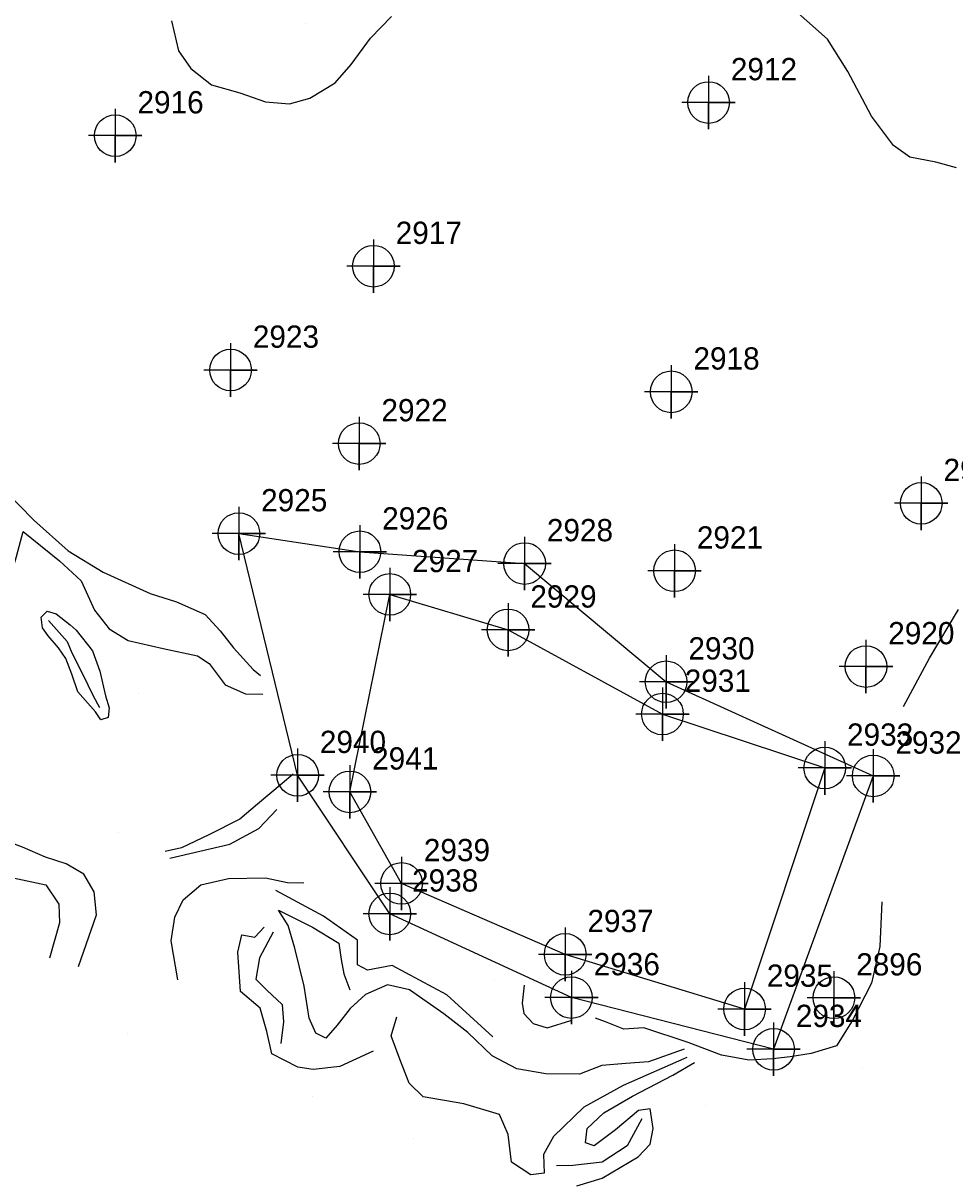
# Model space of a CAD drawing. Extents: x 2062781 to 2066835, y 358981 to 366501.
# Drawn here: x 2064945.6 to 2065050.3, y 363663.1 to 363793 of the extents above; entities that cross this region are included whole.
import ezdxf

# ---------------------------------------------------------------- set-up
doc = ezdxf.new("R2010")
doc.units = 0
for name, color, linetype in [('Exist DTM Breakline', 7, 'Continuous'), ('Exist DTM Breakline Cogo Number', 7, 'Continuous'), ('Exist DTM Breakline Cogo Point CELL', 7, 'Continuous'), ('Exist DTM Regular Point CELL', 7, 'Continuous'), ('Exist DTM Regular Point Cogo Number', 7, 'Continuous'), ('Exist DTM Ridgeline', 7, 'Continuous'), ('Exist DTM Ridgeline Cogo Number', 7, 'Continuous'), ('Exist DTM Ridgeline Cogo Point CELL', 7, 'Continuous'), ('PH Exist DTM Breakline', 7, 'Continuous'), ('PH Exist DTM Point', 7, 'Continuous')]:
    doc.layers.add(name, color=color, linetype=linetype)

msp = doc.modelspace()

# ---------------------------------------------------------------- linework, layer by layer
at = {"layer": 'Exist DTM Breakline'}
msp.add_lwpolyline([(2064986.8, 363728.86), (2065000.09, 363724.88), (2065017.43, 363715.42), (2065035.66, 363709.37), (2065026.65, 363682.3), (2065006.5, 363688.44), (2064988.12, 363696.4), (2064982.31, 363706.69), (2064986.8, 363728.86)], dxfattribs=at)
at = {"layer": 'Exist DTM Breakline Cogo Point CELL'}
for points in [[(2064986.8, 363731.86), (2064986.8, 363725.86), (2064986.8, 363728.86), (2064989.8, 363728.86), (2064983.8, 363728.86)], [(2064986.8, 363731.86), (2064986.8, 363725.86), (2064986.8, 363728.86), (2064989.8, 363728.86), (2064983.8, 363728.86)], [(2064986.8, 363731.86), (2064986.8, 363725.86), (2064986.8, 363728.86), (2064989.8, 363728.86), (2064983.8, 363728.86)], [(2065000.09, 363727.88), (2065000.09, 363721.88), (2065000.09, 363724.88), (2065003.09, 363724.88), (2064997.09, 363724.88)], [(2065000.09, 363727.88), (2065000.09, 363721.88), (2065000.09, 363724.88), (2065003.09, 363724.88), (2064997.09, 363724.88)], [(2065000.09, 363727.88), (2065000.09, 363721.88), (2065000.09, 363724.88), (2065003.09, 363724.88), (2064997.09, 363724.88)], [(2065017.43, 363718.42), (2065017.43, 363712.42), (2065017.43, 363715.42), (2065020.43, 363715.42), (2065014.43, 363715.42)], [(2065017.43, 363718.42), (2065017.43, 363712.42), (2065017.43, 363715.42), (2065020.43, 363715.42), (2065014.43, 363715.42)], [(2065017.43, 363718.42), (2065017.43, 363712.42), (2065017.43, 363715.42), (2065020.43, 363715.42), (2065014.43, 363715.42)], [(2065035.66, 363712.37), (2065035.66, 363706.37), (2065035.66, 363709.37), (2065038.66, 363709.37), (2065032.66, 363709.37)], [(2065035.66, 363712.37), (2065035.66, 363706.37), (2065035.66, 363709.37), (2065038.66, 363709.37), (2065032.66, 363709.37)], [(2065035.66, 363712.37), (2065035.66, 363706.37), (2065035.66, 363709.37), (2065038.66, 363709.37), (2065032.66, 363709.37)], [(2064982.31, 363709.69), (2064982.31, 363703.69), (2064982.31, 363706.69), (2064985.31, 363706.69), (2064979.31, 363706.69)], [(2064982.31, 363709.69), (2064982.31, 363703.69), (2064982.31, 363706.69), (2064985.31, 363706.69), (2064979.31, 363706.69)], [(2064982.31, 363709.69), (2064982.31, 363703.69), (2064982.31, 363706.69), (2064985.31, 363706.69), (2064979.31, 363706.69)], [(2064988.12, 363699.4), (2064988.12, 363693.4), (2064988.12, 363696.4), (2064991.12, 363696.4), (2064985.12, 363696.4)], [(2064988.12, 363699.4), (2064988.12, 363693.4), (2064988.12, 363696.4), (2064991.12, 363696.4), (2064985.12, 363696.4)], [(2064988.12, 363699.4), (2064988.12, 363693.4), (2064988.12, 363696.4), (2064991.12, 363696.4), (2064985.12, 363696.4)], [(2065006.5, 363691.44), (2065006.5, 363685.44), (2065006.5, 363688.44), (2065009.5, 363688.44), (2065003.5, 363688.44)], [(2065006.5, 363691.44), (2065006.5, 363685.44), (2065006.5, 363688.44), (2065009.5, 363688.44), (2065003.5, 363688.44)], [(2065006.5, 363691.44), (2065006.5, 363685.44), (2065006.5, 363688.44), (2065009.5, 363688.44), (2065003.5, 363688.44)], [(2065026.65, 363685.3), (2065026.65, 363679.3), (2065026.65, 363682.3), (2065029.65, 363682.3), (2065023.65, 363682.3)], [(2065026.65, 363685.3), (2065026.65, 363679.3), (2065026.65, 363682.3), (2065029.65, 363682.3), (2065023.65, 363682.3)], [(2065026.65, 363685.3), (2065026.65, 363679.3), (2065026.65, 363682.3), (2065029.65, 363682.3), (2065023.65, 363682.3)]]:
    msp.add_lwpolyline(points, dxfattribs=at)
for centre in [(2064986.8, 363728.86), (2064986.8, 363728.86), (2064986.8, 363728.86), (2065000.09, 363724.88), (2065000.09, 363724.88), (2065000.09, 363724.88), (2065017.43, 363715.42), (2065017.43, 363715.42), (2065017.43, 363715.42), (2065035.66, 363709.37), (2065035.66, 363709.37), (2065035.66, 363709.37), (2064982.31, 363706.69), (2064982.31, 363706.69), (2064982.31, 363706.69), (2064988.12, 363696.4), (2064988.12, 363696.4), (2064988.12, 363696.4), (2065006.5, 363688.44), (2065006.5, 363688.44), (2065006.5, 363688.44), (2065026.65, 363682.3), (2065026.65, 363682.3), (2065026.65, 363682.3)]:
    msp.add_circle(centre, 2.34, dxfattribs=at)
at = {"layer": 'Exist DTM Regular Point CELL'}
for points in [[(2065022.61, 363787.1), (2065022.61, 363781.1), (2065022.61, 363784.1), (2065025.61, 363784.1), (2065019.61, 363784.1)], [(2064955.95, 363783.38), (2064955.95, 363777.38), (2064955.95, 363780.38), (2064958.95, 363780.38), (2064952.95, 363780.38)], [(2064984.96, 363768.72), (2064984.96, 363762.72), (2064984.96, 363765.72), (2064987.96, 363765.72), (2064981.96, 363765.72)], [(2064968.91, 363757.06), (2064968.91, 363751.06), (2064968.91, 363754.06), (2064971.91, 363754.06), (2064965.91, 363754.06)], [(2065018.41, 363754.61), (2065018.41, 363748.61), (2065018.41, 363751.61), (2065021.41, 363751.61), (2065015.41, 363751.61)], [(2064983.36, 363748.8), (2064983.36, 363742.8), (2064983.36, 363745.8), (2064986.36, 363745.8), (2064980.36, 363745.8)], [(2065046.5, 363742.09), (2065046.5, 363736.09), (2065046.5, 363739.09), (2065049.5, 363739.09), (2065043.5, 363739.09)], [(2065018.79, 363734.51), (2065018.79, 363728.51), (2065018.79, 363731.51), (2065021.79, 363731.51), (2065015.79, 363731.51)], [(2065040.29, 363723.76), (2065040.29, 363717.76), (2065040.29, 363720.76), (2065043.29, 363720.76), (2065037.29, 363720.76)], [(2065036.69, 363686.57), (2065036.69, 363680.57), (2065036.69, 363683.57), (2065039.69, 363683.57), (2065033.69, 363683.57)]]:
    msp.add_lwpolyline(points, dxfattribs=at)
for centre in [(2065022.61, 363784.1), (2064955.95, 363780.38), (2064984.96, 363765.72), (2064968.91, 363754.06), (2065018.41, 363751.61), (2064983.36, 363745.8), (2065046.5, 363739.09), (2065018.79, 363731.51), (2065040.29, 363720.76), (2065036.69, 363683.57)]:
    msp.add_circle(centre, 2.34, dxfattribs=at)
at = {"layer": 'Exist DTM Ridgeline'}
msp.add_lwpolyline([(2064969.84, 363735.69), (2064983.44, 363733.65), (2065001.94, 363732.33), (2065017.84, 363719.05), (2065041.1, 363708.48), (2065029.91, 363677.78), (2065007.2, 363683.59), (2064986.8, 363692.99), (2064976.44, 363708.55), (2064969.84, 363735.69)], dxfattribs=at)
at = {"layer": 'Exist DTM Ridgeline Cogo Point CELL'}
for points in [[(2064969.84, 363738.69), (2064969.84, 363732.69), (2064969.84, 363735.69), (2064972.84, 363735.69), (2064966.84, 363735.69)], [(2064969.84, 363738.69), (2064969.84, 363732.69), (2064969.84, 363735.69), (2064972.84, 363735.69), (2064966.84, 363735.69)], [(2064969.84, 363738.69), (2064969.84, 363732.69), (2064969.84, 363735.69), (2064972.84, 363735.69), (2064966.84, 363735.69)], [(2064983.44, 363736.65), (2064983.44, 363730.65), (2064983.44, 363733.65), (2064986.44, 363733.65), (2064980.44, 363733.65)], [(2064983.44, 363736.65), (2064983.44, 363730.65), (2064983.44, 363733.65), (2064986.44, 363733.65), (2064980.44, 363733.65)], [(2064983.44, 363736.65), (2064983.44, 363730.65), (2064983.44, 363733.65), (2064986.44, 363733.65), (2064980.44, 363733.65)], [(2065001.94, 363735.33), (2065001.94, 363729.33), (2065001.94, 363732.33), (2065004.94, 363732.33), (2064998.94, 363732.33)], [(2065001.94, 363735.33), (2065001.94, 363729.33), (2065001.94, 363732.33), (2065004.94, 363732.33), (2064998.94, 363732.33)], [(2065001.94, 363735.33), (2065001.94, 363729.33), (2065001.94, 363732.33), (2065004.94, 363732.33), (2064998.94, 363732.33)], [(2065017.84, 363722.05), (2065017.84, 363716.05), (2065017.84, 363719.05), (2065020.84, 363719.05), (2065014.84, 363719.05)], [(2065017.84, 363722.05), (2065017.84, 363716.05), (2065017.84, 363719.05), (2065020.84, 363719.05), (2065014.84, 363719.05)], [(2065017.84, 363722.05), (2065017.84, 363716.05), (2065017.84, 363719.05), (2065020.84, 363719.05), (2065014.84, 363719.05)], [(2064976.44, 363711.55), (2064976.44, 363705.55), (2064976.44, 363708.55), (2064979.44, 363708.55), (2064973.44, 363708.55)], [(2064976.44, 363711.55), (2064976.44, 363705.55), (2064976.44, 363708.55), (2064979.44, 363708.55), (2064973.44, 363708.55)], [(2064976.44, 363711.55), (2064976.44, 363705.55), (2064976.44, 363708.55), (2064979.44, 363708.55), (2064973.44, 363708.55)], [(2065041.1, 363711.48), (2065041.1, 363705.48), (2065041.1, 363708.48), (2065044.1, 363708.48), (2065038.1, 363708.48)], [(2065041.1, 363711.48), (2065041.1, 363705.48), (2065041.1, 363708.48), (2065044.1, 363708.48), (2065038.1, 363708.48)], [(2065041.1, 363711.48), (2065041.1, 363705.48), (2065041.1, 363708.48), (2065044.1, 363708.48), (2065038.1, 363708.48)], [(2064986.8, 363695.99), (2064986.8, 363689.99), (2064986.8, 363692.99), (2064989.8, 363692.99), (2064983.8, 363692.99)], [(2064986.8, 363695.99), (2064986.8, 363689.99), (2064986.8, 363692.99), (2064989.8, 363692.99), (2064983.8, 363692.99)], [(2064986.8, 363695.99), (2064986.8, 363689.99), (2064986.8, 363692.99), (2064989.8, 363692.99), (2064983.8, 363692.99)], [(2065007.2, 363686.59), (2065007.2, 363680.59), (2065007.2, 363683.59), (2065010.2, 363683.59), (2065004.2, 363683.59)], [(2065007.2, 363686.59), (2065007.2, 363680.59), (2065007.2, 363683.59), (2065010.2, 363683.59), (2065004.2, 363683.59)], [(2065007.2, 363686.59), (2065007.2, 363680.59), (2065007.2, 363683.59), (2065010.2, 363683.59), (2065004.2, 363683.59)], [(2065029.91, 363680.78), (2065029.91, 363674.78), (2065029.91, 363677.78), (2065032.91, 363677.78), (2065026.91, 363677.78)], [(2065029.91, 363680.78), (2065029.91, 363674.78), (2065029.91, 363677.78), (2065032.91, 363677.78), (2065026.91, 363677.78)], [(2065029.91, 363680.78), (2065029.91, 363674.78), (2065029.91, 363677.78), (2065032.91, 363677.78), (2065026.91, 363677.78)]]:
    msp.add_lwpolyline(points, dxfattribs=at)
for centre in [(2064969.84, 363735.69), (2064969.84, 363735.69), (2064969.84, 363735.69), (2064983.44, 363733.65), (2064983.44, 363733.65), (2064983.44, 363733.65), (2065001.94, 363732.33), (2065001.94, 363732.33), (2065001.94, 363732.33), (2065017.84, 363719.05), (2065017.84, 363719.05), (2065017.84, 363719.05), (2064976.44, 363708.55), (2064976.44, 363708.55), (2064976.44, 363708.55), (2065041.1, 363708.48), (2065041.1, 363708.48), (2065041.1, 363708.48), (2064986.8, 363692.99), (2064986.8, 363692.99), (2064986.8, 363692.99), (2065007.2, 363683.59), (2065007.2, 363683.59), (2065007.2, 363683.59), (2065029.91, 363677.78), (2065029.91, 363677.78), (2065029.91, 363677.78)]:
    msp.add_circle(centre, 2.34, dxfattribs=at)
at = {"layer": 'PH Exist DTM Breakline'}
for points in [[(2065050.45, 363776.76), (2065048.13, 363777.41), (2065045.21, 363777.98), (2065043.39, 363779.27), (2065040.9, 363782.56), (2065038.25, 363787.57), (2065035.97, 363791.21), (2065031.33, 363795.34)], [(2064962.27, 363793.29), (2064963.06, 363789.89), (2064964.45, 363787.91), (2064966.77, 363786.1), (2064969.94, 363785.18), (2064972.82, 363784.19), (2064975.52, 363783.96), (2064977.82, 363784.59), (2064980.67, 363786.32), (2064982.44, 363788.36), (2064984.61, 363791.32), (2064986.97, 363793.75)], [(2064943.49, 363740.6), (2064946.82, 363737.21), (2064950.68, 363733.75), (2064954.61, 363731.36), (2064959.88, 363728.97), (2064962.85, 363728.03), (2064966.06, 363726.6), (2064967.74, 363724.76), (2064969.23, 363722.85), (2064971.44, 363720.42), (2064972.26, 363719.75)], [(2064951.81, 363687.08), (2064953.84, 363692.86), (2064953.59, 363695.45), (2064952.41, 363697.45), (2064950.45, 363698.62), (2064948.1, 363699.34), (2064945.55, 363700.46), (2064943.63, 363701.18), (2064942.52, 363701.99), (2064942.06, 363704.37), (2064941.72, 363710.85), (2064941.42, 363714.92), (2064940.45, 363719.52), (2064939.41, 363722.5), (2064939.75, 363724.3), (2064942.43, 363727.21), (2064944.49, 363731.85), (2064944.85, 363733.11), (2064945.61, 363735.91)], [(2064945.61, 363735.91), (2064949.69, 363732.65), (2064952.12, 363730.37), (2064953.64, 363727.09), (2064955.26, 363725.01), (2064957.39, 363723.69), (2064961.34, 363722.8), (2064965.2, 363721.96), (2064966.52, 363721.11), (2064968.29, 363718.7), (2064970.59, 363717.71), (2064972.52, 363717.67)], [(2065044.52, 363716.26), (2065047.44, 363721.71), (2065050.7, 363727.16)], [(2064953.73, 363715.66), (2064951.74, 363717.93), (2064951.08, 363719.92), (2064950.41, 363721.67), (2064949.59, 363722.88), (2064948.4, 363724.22), (2064947.78, 363725.12), (2064947.62, 363726.29), (2064948.29, 363726.97), (2064949.33, 363726.68), (2064950.9, 363725.44), (2064951.55, 363724.84), (2064953.38, 363722.52), (2064954.24, 363720.25), (2064954.84, 363717.49), (2064955.28, 363716.13), (2064955.16, 363715.05), (2064954.33, 363714.79), (2064953.73, 363715.66)], [(2064948.46, 363725.94), (2064950.57, 363723.57), (2064951.08, 363722.29), (2064952.26, 363719.96), (2064953.46, 363717.47), (2064954.2, 363716.17)], [(2064975.94, 363708.69), (2064974.72, 363707.62), (2064971.93, 363705.32), (2064969.96, 363703.63), (2064966.46, 363701.88), (2064963.4, 363700.4), (2064961.57, 363699.98)], [(2064962.08, 363699.25), (2064968.82, 363700.81), (2064972.07, 363702.56), (2064974.09, 363704.7)], [(2064944.5, 363697.04), (2064948.17, 363696.23), (2064949.63, 363694.08), (2064949.69, 363691.97), (2064948.56, 363688.02)], [(2064962.99, 363685.57), (2064962.25, 363689.97), (2064962.63, 363692.62), (2064963.6, 363694.55), (2064965.57, 363696.26), (2064968.67, 363696.96), (2064972.84, 363697.05), (2064975.3, 363696.52), (2064977.13, 363696.48)], [(2064998.36, 363679.16), (2064993.19, 363683.9), (2064987.06, 363687.18), (2064984.3, 363686.67), (2064983.17, 363687.27), (2064983.16, 363690.03), (2064979.33, 363692.72), (2064974, 363695.6)], [(2065019.87, 363677.78), (2065015.86, 363676.36), (2065013.31, 363676.18), (2065010.63, 363675.94), (2065008.1, 363674.98), (2065004.33, 363675.04), (2065001.06, 363675.59), (2064998.3, 363677.05), (2064995.57, 363679.65), (2064992.87, 363681.77), (2064989, 363684.45), (2064986.52, 363685.01), (2064984.08, 363683.94), (2064982.35, 363682.36), (2064980.89, 363680.48), (2064979.6, 363679.03), (2064978.5, 363679.58), (2064977.74, 363681.27), (2064977.16, 363684.88), (2064976.14, 363689.14), (2064975.37, 363691.69), (2064974.31, 363693.41), (2064978.11, 363691.5), (2064981.07, 363689.69), (2064981.35, 363687.86), (2064981.65, 363686.25), (2064982.31, 363684.45)], [(2065042.09, 363694.32), (2065041.83, 363689.31), (2065040.92, 363685.22), (2065038.73, 363680.99), (2065036.98, 363678.15), (2065034.14, 363677.29), (2065031.77, 363676.92), (2065029.81, 363676.71), (2065027.18, 363676.55), (2065024.05, 363677.11), (2065020.33, 363678.53), (2065015.35, 363680.2), (2065013.09, 363680.04), (2065011.01, 363680.87), (2065009.92, 363681.26)], [(2064984.93, 363677.58), (2064981.17, 363675.83), (2064978.17, 363675.51), (2064976.48, 363675.76), (2064973.55, 363677.28), (2064972.98, 363679.79), (2064972.22, 363682.38), (2064970.04, 363684.26), (2064969.73, 363688.67), (2064970.19, 363690.63), (2064971.64, 363690.36), (2064972.68, 363691.49)], [(2064973.7, 363690.95), (2064972.15, 363688.05), (2064971.74, 363685.65), (2064973, 363684.41), (2064974.69, 363682.82), (2064974.84, 363680.85), (2064974.57, 363678.44)], [(2065001.88, 363684.97), (2065001.68, 363682.95), (2065001.85, 363681.81), (2065002.9, 363680.67), (2065004.49, 363680.2), (2065007.14, 363681.01)], [(2065020.16, 363676.87), (2065013.03, 363673.73), (2065008.59, 363671.29), (2065005.17, 363668), (2065004.07, 363665.95), (2065004.12, 363663.85), (2065002.64, 363663.68), (2065000.46, 363665.11), (2065000.11, 363668.21), (2064999.12, 363670.46), (2064995.1, 363671.67), (2064990.53, 363672.44), (2064988.98, 363673.98), (2064987.92, 363676.68), (2064986.96, 363679.28), (2064987.6, 363681.42)], [(2065007.82, 363662.45), (2065010.64, 363663.31), (2065014.68, 363665.72), (2065016.05, 363667.12), (2065016.4, 363668.9), (2065016.04, 363671.11), (2065014.72, 363670.89), (2065012.15, 363668.73), (2065009.76, 363666.94), (2065008.8, 363667.28), (2065008.97, 363668.89), (2065010.83, 363670.64), (2065014.07, 363672.53), (2065018.59, 363674.88), (2065021.04, 363676.31)], [(2065015.1, 363669.98), (2065013.48, 363666.94), (2065010.65, 363665.1), (2065007.35, 363664.72), (2065005.52, 363664.69)]]:
    msp.add_lwpolyline(points, dxfattribs=at)
at = {"layer": 'PH Exist DTM Point'}
for p, q in [((2064977.36, 363792.93), (2064977.36, 363792.93)), ((2064958.53, 363717.76), (2064958.53, 363717.76)), ((2064956.27, 363702.16), (2064956.27, 363702.16)), ((2064998.56, 363685.61), (2064998.56, 363685.61)), ((2064957.32, 363679.59), (2064957.32, 363679.59)), ((2065039.88, 363675.7), (2065039.88, 363675.7)), ((2064978.07, 363672.43), (2064978.07, 363672.43)), ((2065022.3, 363671.42), (2065022.3, 363671.42)), ((2064989.44, 363667.71), (2064989.44, 363667.71))]:
    msp.add_line(p, q, dxfattribs=at)

# ---------------------------------------------------------------- texts
at = {"layer": 'Exist DTM Breakline Cogo Number'}
for s, p in [('2927', (2064989.3, 363731.36)), ('2927', (2064989.3, 363731.36)), ('2927', (2064989.3, 363731.36)), ('2929', (2065002.59, 363727.38)), ('2929', (2065002.59, 363727.38)), ('2929', (2065002.59, 363727.38)), ('2931', (2065019.93, 363717.92)), ('2931', (2065019.93, 363717.92)), ('2931', (2065019.93, 363717.92)), ('2933', (2065038.16, 363711.87)), ('2933', (2065038.16, 363711.87)), ('2933', (2065038.16, 363711.87)), ('2941', (2064984.81, 363709.19)), ('2941', (2064984.81, 363709.19)), ('2941', (2064984.81, 363709.19)), ('2939', (2064990.62, 363698.9)), ('2939', (2064990.62, 363698.9)), ('2939', (2064990.62, 363698.9)), ('2937', (2065009, 363690.94)), ('2937', (2065009, 363690.94)), ('2937', (2065009, 363690.94)), ('2935', (2065029.15, 363684.8)), ('2935', (2065029.15, 363684.8)), ('2935', (2065029.15, 363684.8))]:
    msp.add_text(s, height=2.5, dxfattribs=at).set_placement(p)
at = {"layer": 'Exist DTM Regular Point Cogo Number'}
for s, p in [('2912', (2065025.11, 363786.6)), ('2912', (2065025.11, 363786.6)), ('2912', (2065025.11, 363786.6)), ('2916', (2064958.45, 363782.88)), ('2916', (2064958.45, 363782.88)), ('2916', (2064958.45, 363782.88)), ('2917', (2064987.46, 363768.22)), ('2917', (2064987.46, 363768.22)), ('2917', (2064987.46, 363768.22)), ('2923', (2064971.41, 363756.56)), ('2923', (2064971.41, 363756.56)), ('2923', (2064971.41, 363756.56)), ('2918', (2065020.91, 363754.11)), ('2918', (2065020.91, 363754.11)), ('2918', (2065020.91, 363754.11)), ('2922', (2064985.86, 363748.3)), ('2922', (2064985.86, 363748.3)), ('2922', (2064985.86, 363748.3)), ('2919', (2065049, 363741.59)), ('2919', (2065049, 363741.59)), ('2919', (2065049, 363741.59)), ('2921', (2065021.29, 363734.01)), ('2921', (2065021.29, 363734.01)), ('2921', (2065021.29, 363734.01)), ('2920', (2065042.79, 363723.26)), ('2920', (2065042.79, 363723.26)), ('2920', (2065042.79, 363723.26)), ('2896', (2065039.19, 363686.07)), ('2896', (2065039.19, 363686.07)), ('2896', (2065039.19, 363686.07))]:
    msp.add_text(s, height=2.5, dxfattribs=at).set_placement(p)
at = {"layer": 'Exist DTM Ridgeline Cogo Number'}
for s, p in [('2925', (2064972.34, 363738.19)), ('2925', (2064972.34, 363738.19)), ('2925', (2064972.34, 363738.19)), ('2926', (2064985.94, 363736.15)), ('2926', (2064985.94, 363736.15)), ('2926', (2064985.94, 363736.15)), ('2928', (2065004.44, 363734.83)), ('2928', (2065004.44, 363734.83)), ('2928', (2065004.44, 363734.83)), ('2930', (2065020.34, 363721.55)), ('2930', (2065020.34, 363721.55)), ('2930', (2065020.34, 363721.55)), ('2940', (2064978.94, 363711.05)), ('2940', (2064978.94, 363711.05)), ('2940', (2064978.94, 363711.05)), ('2932', (2065043.6, 363710.98)), ('2932', (2065043.6, 363710.98)), ('2932', (2065043.6, 363710.98)), ('2938', (2064989.3, 363695.49)), ('2938', (2064989.3, 363695.49)), ('2938', (2064989.3, 363695.49)), ('2936', (2065009.7, 363686.09)), ('2936', (2065009.7, 363686.09)), ('2936', (2065009.7, 363686.09)), ('2934', (2065032.41, 363680.28)), ('2934', (2065032.41, 363680.28)), ('2934', (2065032.41, 363680.28))]:
    msp.add_text(s, height=2.5, dxfattribs=at).set_placement(p)

doc.saveas('drawing.dxf')
